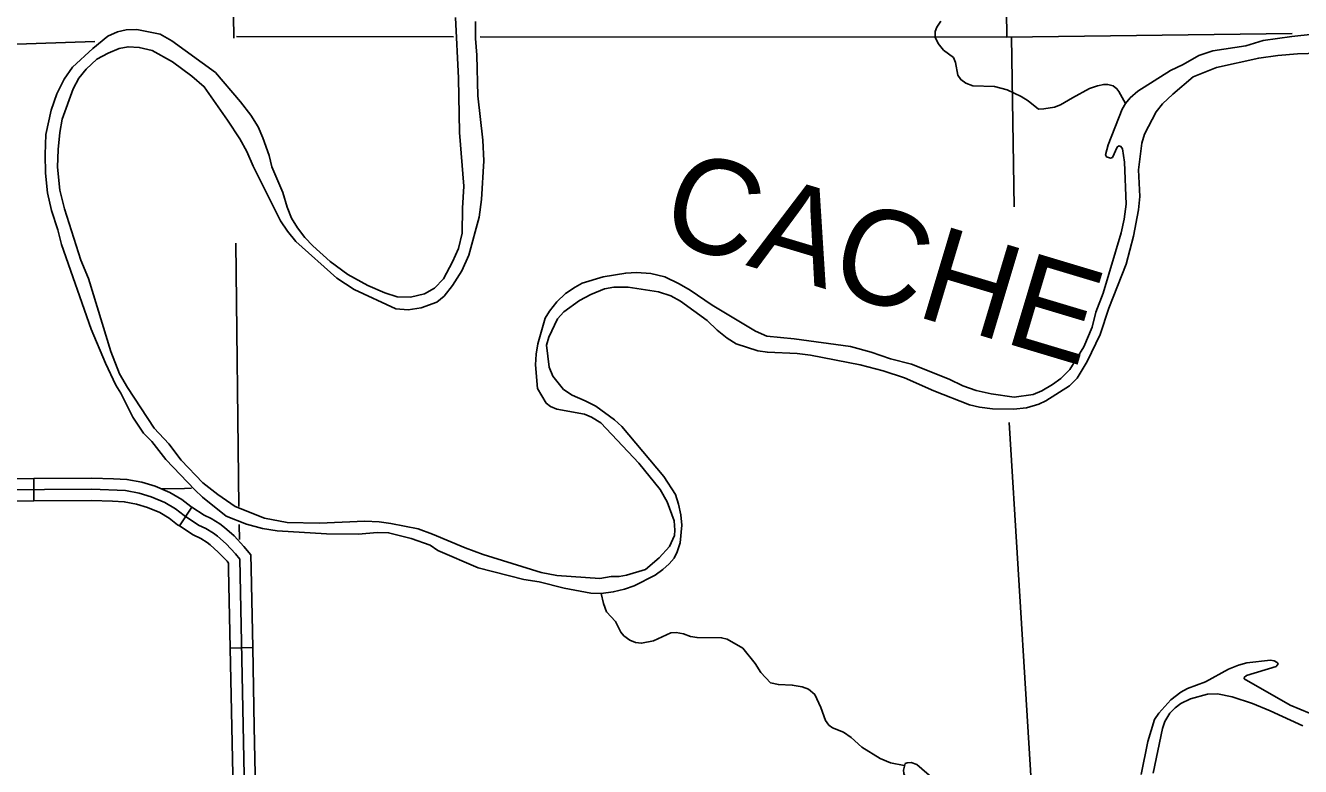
# Model space of a CAD drawing. Extents: x 1084508 to 1142749, y 1057638 to 1093403.
# Drawn here: x 1087461 to 1090132, y 1065503 to 1067055 of the extents above; entities that cross this region are included whole.
import ezdxf

# ---------------------------------------------------------------- set-up
doc = ezdxf.new("R2010")
doc.units = 0
for name, color, linetype in [('Level 35', 7, 'Continuous'), ('Level 4', 7, 'Continuous'), ('Level 45', 7, 'Continuous'), ('Level 5', 7, 'Continuous'), ('Level 7', 7, 'Continuous'), ('Level 9', 7, 'Continuous')]:
    doc.layers.add(name, color=color, linetype=linetype)

msp = doc.modelspace()

# ---------------------------------------------------------------- linework, layer by layer
at = {"layer": 'Level 35'}
for points in [[(1089765.6, 1066892), (1089751.9, 1066917.3), (1089747.7, 1066922.9), (1089739.7, 1066928.9), (1089728.6, 1066932), (1089720.1, 1066932), (1089706.7, 1066929.1), (1089690.3, 1066923.2), (1089654.6, 1066904.1), (1089629.7, 1066889.1), (1089616.7, 1066884), (1089594.2, 1066880.7), (1089583.6, 1066880.4), (1089561.7, 1066897.6), (1089547.3, 1066906.9), (1089517.4, 1066920.3), (1089491.5, 1066927.4), (1089446, 1066929.3), (1089431.4, 1066934.8), (1089420.8, 1066942), (1089414.6, 1066951.6), (1089409.7, 1066978.1), (1089404.9, 1066988.3), (1089384.4, 1067003.4), (1089373, 1067017.5), (1089366.6, 1067030.8), (1089366.5, 1067042.7), (1089370.3, 1067052), (1089378.4, 1067064.2)], [(1089302.2, 1065504.4), (1089273.1, 1065510.6), (1089251.9, 1065519.1), (1089213.5, 1065543.3), (1089190.9, 1065563.6), (1089174.9, 1065574.4), (1089151.4, 1065584), (1089144.3, 1065589.4), (1089136.8, 1065599.2), (1089127.2, 1065626), (1089114.4, 1065653.5), (1089101.5, 1065664.4), (1089087.8, 1065669.9), (1089067.4, 1065673.4), (1089038.5, 1065674.3), (1089022.1, 1065678.2), (1089001.3, 1065699.5), (1088989.5, 1065718.3), (1088963.7, 1065750.5), (1088930.8, 1065769.5), (1088919.4, 1065772.3), (1088868, 1065772.8), (1088854.4, 1065775.2), (1088839.6, 1065780.4), (1088823.8, 1065783.3), (1088813.1, 1065782.9), (1088776.7, 1065766), (1088751.5, 1065760.8), (1088738.9, 1065762.3), (1088726.8, 1065767.5), (1088714.7, 1065776.3), (1088708.1, 1065783.9), (1088696.7, 1065806.8), (1088678.2, 1065826.9), (1088671.7, 1065844.3), (1088667, 1065865.3)], [(1089387.7, 1065303.6), (1089397.6, 1065362.5), (1089395.9, 1065395.5), (1089387.1, 1065437), (1089378.3, 1065455.9), (1089364.5, 1065475.3), (1089328.7, 1065507.1), (1089316.7, 1065511.1), (1089308.2, 1065510.5), (1089304.2, 1065508.8), (1089300.3, 1065495.2), (1089301.5, 1065488), (1089324.3, 1065439.7), (1089336.5, 1065421.8), (1089342.3, 1065405), (1089344.2, 1065375.2), (1089339.6, 1065344.3), (1089334.2, 1065325.5), (1089326.4, 1065281.4)]]:
    msp.add_lwpolyline(points, dxfattribs=at)
at = {"layer": 'Level 4'}
for points in [[(1088357.4, 1067031.7), (1087903, 1067032)], [(1090114.7, 1067038.8), (1089516.4, 1067031), (1088413.2, 1067031.7)], [(1087606.3, 1067022), (1086867.5, 1066996.4)]]:
    msp.add_lwpolyline(points, dxfattribs=at)
at = {"layer": 'Level 45'}
for p, q in [((1087478.1, 1066106.3), (1087478.4, 1066059.2)), ((1087809.5, 1066045.9), (1087783.4, 1066006.7)), ((1087936.8, 1065751.7), (1087889.7, 1065750.7))]:
    msp.add_line(p, q, dxfattribs=at)
for points in [[(1087478.1, 1066106.3), (1087312.4, 1066105.2)], [(1087644.9, 1066105.4), (1087600, 1066107.1), (1087478.1, 1066106.3)], [(1087809.5, 1066045.9), (1087807.1, 1066047.5), (1087788.5, 1066061.9), (1087763.3, 1066077), (1087732.1, 1066090.2), (1087704.3, 1066098.4), (1087673.1, 1066104.3), (1087644.9, 1066105.4)], [(1087670.4, 1066080.8), (1087599.6, 1066083.6), (1087104.7, 1066080.2), (1086147.2, 1066060.1)], [(1087909.5, 1065937.3), (1087900.7, 1065948.2), (1087881.2, 1065968.9), (1087863, 1065985.2), (1087854.5, 1065991.7), (1087838.9, 1066001.2), (1087823.2, 1066008.5), (1087793.3, 1066028.4), (1087775.2, 1066042.4), (1087752.6, 1066056), (1087724.2, 1066068), (1087698.7, 1066075.4), (1087670.4, 1066080.8)], [(1087478.4, 1066059.2), (1087312.7, 1066058.1)], [(1087643, 1066058.3), (1087599.2, 1066060), (1087478.4, 1066059.2)], [(1087783.4, 1066006.7), (1087779.5, 1066009.3), (1087761.9, 1066023), (1087742, 1066034.9), (1087716.3, 1066045.7), (1087693.2, 1066052.5), (1087667.8, 1066057.4), (1087643, 1066058.3)], [(1087933.5, 1065917.3), (1087932.9, 1065945.9), (1087918.4, 1065963.7), (1087897.6, 1065985.8), (1087878, 1066003.4), (1087867.8, 1066011.2), (1087850, 1066022), (1087834.8, 1066029.1), (1087809.5, 1066045.9)], [(1087886.4, 1065916.4), (1087886.1, 1065928.7), (1087883, 1065932.7), (1087864.7, 1065952.1), (1087848, 1065967), (1087841.1, 1065972.3), (1087827.8, 1065980.4), (1087811.7, 1065987.9), (1087783.4, 1066006.7)], [(1087923.6, 1065240.9), (1087909.5, 1065937.3)], [(1087889.7, 1065750.7), (1087886.4, 1065916.4)], [(1087936.8, 1065751.7), (1087933.5, 1065917.3)], [(1087893.1, 1065585), (1087889.7, 1065750.7)], [(1087940.2, 1065586), (1087936.8, 1065751.7)], [(1087896.5, 1065419.3), (1087893.1, 1065585)], [(1087943.5, 1065420.3), (1087940.2, 1065586)]]:
    msp.add_lwpolyline(points, dxfattribs=at)
at = {"layer": 'Level 5'}
for points in [[(1089501.6, 1068232), (1089517.2, 1067031)], [(1087897.2, 1067029), (1087897.2, 1067032), (1087890.2, 1067442.6)], [(1089526.8, 1067031.1), (1089532.2, 1066675.2)], [(1087901.4, 1066599.2), (1087908, 1066047.2)], [(1089521.6, 1066223.4), (1089578.2, 1065301.8)], [(1087908.5, 1066009.8), (1087908.9, 1065978)]]:
    msp.add_lwpolyline(points, dxfattribs=at)
at = {"layer": 'Level 7'}
msp.add_lwpolyline([(1087808.6, 1066086), (1087793.6, 1066085.1), (1087747.3, 1066084.5)], dxfattribs=at)
at = {"layer": 'Level 9'}
for points in [[(1087994.8, 1066646.3), (1088009.6, 1066624.7), (1088027.5, 1066602.7), (1088113, 1066525.6), (1088149.2, 1066502.3), (1088237, 1066461.5), (1088262.5, 1066459.5), (1088289.9, 1066463.8), (1088322.4, 1066475.6), (1088337.7, 1066488.3), (1088355.5, 1066510.6), (1088374.8, 1066541.4), (1088389.4, 1066574.3), (1088411.3, 1066653.9), (1088416.4, 1066690.6), (1088421, 1066771.9), (1088419.3, 1066814.9), (1088408.5, 1066907.9), (1088406.7, 1066993.1), (1088403.4, 1067027.9), (1088403.8, 1067063.7)], [(1088030.4, 1066631.7), (1088046.1, 1066611.2), (1088062.6, 1066593.5), (1088099.4, 1066561), (1088136, 1066533.3), (1088177.8, 1066510.5), (1088213.4, 1066495.3), (1088239.6, 1066487), (1088267.5, 1066486.4), (1088296.8, 1066493), (1088317.7, 1066504.7), (1088336.5, 1066524.5), (1088355.7, 1066560.3), (1088368.3, 1066588.1), (1088375.7, 1066620.4), (1088376.6, 1066672.6), (1088379.5, 1066718.6), (1088370.2, 1066831.2), (1088367.8, 1066945.2), (1088361.9, 1067072.4)], [(1088823, 1066072.5), (1088829.2, 1066052.6), (1088833.7, 1066029.8), (1088835.7, 1066008.2), (1088832.2, 1065971.3), (1088826.5, 1065952.2), (1088819.7, 1065939.1), (1088809.5, 1065927.1), (1088796.4, 1065915.1), (1088780.1, 1065903.5), (1088736, 1065881), (1088715.6, 1065874.1), (1088692.3, 1065868.6), (1088667, 1065865.3), (1088645.4, 1065865.5), (1088589.5, 1065876.2), (1088537.1, 1065889.3), (1088504.7, 1065894.5), (1088409.5, 1065919.1), (1088324.4, 1065955), (1088308.4, 1065966.4), (1088268.8, 1065980.2), (1088221.4, 1065992.5), (1088198.5, 1065993), (1088158.1, 1065989.8), (1088091.1, 1065990.4), (1087988.1, 1065996.5), (1087957.2, 1066001.4), (1087923.7, 1066010.4), (1087881.2, 1066027.2), (1087831.6, 1066067.1), (1087815.2, 1066082.3), (1087754.8, 1066145.7), (1087725.1, 1066183.7), (1087707.9, 1066201.1), (1087685.9, 1066234.6), (1087660.8, 1066284.7), (1087650.2, 1066302), (1087628.3, 1066347.5), (1087598.5, 1066418.9), (1087536, 1066596.7), (1087528.8, 1066626.9), (1087515.3, 1066668), (1087506.9, 1066704.5), (1087502.7, 1066746.2), (1087502.1, 1066784.8), (1087503.6, 1066826.7), (1087514.5, 1066878), (1087526.5, 1066912.3), (1087541.9, 1066942.7), (1087559.5, 1066967.8), (1087601.5, 1067006.9), (1087633.3, 1067033.1), (1087653.4, 1067042.3), (1087671.7, 1067046.6), (1087693.9, 1067047.1), (1087742.8, 1067037.3), (1087767.1, 1067023.4), (1087858.5, 1066956.9), (1087911, 1066895.4), (1087933.2, 1066867.2), (1087948.4, 1066842.8), (1087958.2, 1066820.2), (1087971.3, 1066783.2), (1087977.1, 1066759.2), (1087999.8, 1066705.5), (1088009.2, 1066674.7), (1088018.4, 1066651.4), (1088030.4, 1066631.7)], [(1090197.1, 1067041.5), (1090114.2, 1067032.6), (1090054.1, 1067023.8), (1090017.7, 1067012.8), (1089948.8, 1067002.1), (1089919.4, 1066992.6), (1089886.7, 1066973.9), (1089860.2, 1066961.1), (1089791.7, 1066918), (1089775.6, 1066903.6), (1089765.6, 1066892), (1089758.5, 1066879.8), (1089729.2, 1066805), (1089723.9, 1066784.4), (1089725.6, 1066780), (1089734.5, 1066777.5), (1089738.2, 1066778.5), (1089747.9, 1066800.5), (1089751.5, 1066802.9), (1089755.9, 1066802.1), (1089759.2, 1066797.1), (1089763.9, 1066768.7), (1089767.1, 1066680.8), (1089763, 1066649.8), (1089756.7, 1066621), (1089719.1, 1066494.3), (1089703.8, 1066454.5), (1089695.7, 1066423.1), (1089678.6, 1066381.7), (1089648.8, 1066334.2), (1089629.9, 1066315.9), (1089612.5, 1066302.8), (1089590.3, 1066289.8), (1089572.4, 1066282), (1089532.1, 1066276.9), (1089484.3, 1066283.8), (1089452.7, 1066290.3), (1089424.8, 1066300.4), (1089396.5, 1066314.3), (1089317.2, 1066345.6), (1089273.2, 1066357.1), (1089232.7, 1066370.8), (1089189.4, 1066382.9), (1089071.3, 1066398.9), (1089013.8, 1066404.5), (1088990.3, 1066414.8), (1088899.5, 1066469.3), (1088853.7, 1066500.8), (1088830.7, 1066513.9), (1088800.2, 1066528.7), (1088770.8, 1066535.6), (1088741, 1066537.7), (1088718.4, 1066536.7), (1088671.4, 1066528.5), (1088627, 1066515.1), (1088612.2, 1066507.4), (1088592, 1066493.8), (1088574.3, 1066476.6), (1088559, 1066456.9), (1088549.4, 1066441.8), (1088534.6, 1066388.2)], [(1088534.6, 1066388.2), (1088530.8, 1066367), (1088529.4, 1066344.3), (1088533.5, 1066294.5), (1088552, 1066264), (1088560.7, 1066257), (1088574.4, 1066251.5), (1088632, 1066241.1), (1088647, 1066234.7), (1088666.2, 1066222.7), (1088746, 1066138.2), (1088790.7, 1066083.1), (1088805.6, 1066057.5), (1088820, 1066017.1), (1088821.3, 1065997.7), (1088820.4, 1065986.9), (1088809.9, 1065963.3), (1088788.7, 1065940), (1088759.7, 1065915.1), (1088719.7, 1065903.5), (1088704.7, 1065901.1), (1088687.8, 1065900.5), (1088664.4, 1065896.9), (1088573.9, 1065903.1), (1088541.5, 1065908.9), (1088419.9, 1065947.1), (1088381.9, 1065960.6), (1088313.3, 1065989.8), (1088283.5, 1066000.8), (1088226.1, 1066012.1), (1088201.8, 1066015.4), (1088171.7, 1066016.9), (1088076.9, 1066012.6), (1088008.8, 1066014.1), (1087961.5, 1066023.2), (1087900, 1066047.3), (1087864, 1066072.6), (1087832.5, 1066097.3), (1087787.2, 1066144.6), (1087761.3, 1066178.9), (1087730.2, 1066211.6), (1087674.5, 1066296.5), (1087657.6, 1066325.2), (1087639.8, 1066372.4), (1087592.6, 1066524.9), (1087576.9, 1066563.7), (1087542.7, 1066671.4), (1087532.7, 1066710.4), (1087528, 1066758.6), (1087529.4, 1066795.2), (1087532.9, 1066831.1), (1087537.6, 1066858.9), (1087560.4, 1066922.9), (1087572.2, 1066944.7), (1087587.9, 1066964), (1087610.1, 1066984.6), (1087634.1, 1066997.3), (1087657.3, 1067006.9), (1087675.7, 1067010.9), (1087699.2, 1067009.5), (1087725.8, 1067002.8), (1087768.8, 1066979.4), (1087809.3, 1066949.3), (1087835.4, 1066927.2), (1087884.3, 1066856.8), (1087909.7, 1066817.7), (1087924.6, 1066791.4), (1087937.5, 1066760.4), (1087994.8, 1066646.3)], [(1090171, 1066997.4), (1090126.4, 1066995.7), (1090085.1, 1066992.4), (1090044.9, 1066987), (1089956.2, 1066967.7), (1089907.3, 1066947.6), (1089864.6, 1066911.3), (1089843.3, 1066891.4), (1089829.8, 1066874.6), (1089805.6, 1066827.6), (1089800.2, 1066808.9), (1089792.6, 1066752.7), (1089795.4, 1066697.1), (1089793.1, 1066669), (1089782.4, 1066614), (1089767, 1066555), (1089730.8, 1066462.9), (1089712.5, 1066407.9), (1089685.5, 1066351.4), (1089664.4, 1066316.7), (1089648.6, 1066300.5), (1089598.8, 1066269), (1089584, 1066261.6), (1089557.9, 1066254.1), (1089531.1, 1066251.1), (1089486.9, 1066252.1), (1089459.5, 1066255.9), (1089438.7, 1066260.6), (1089363.8, 1066289.9), (1089302.7, 1066316.8), (1089257.8, 1066331.4), (1089209.7, 1066344.3), (1089105.3, 1066364.8), (1089077.7, 1066368), (1089015.2, 1066370.6), (1088995, 1066374), (1088950.1, 1066388), (1088930.9, 1066400.2), (1088910.3, 1066416.9), (1088889, 1066437.5), (1088833.1, 1066477.9), (1088812.7, 1066489.1), (1088786.8, 1066497.4), (1088723.8, 1066507), (1088693.7, 1066507.2), (1088673.7, 1066503.8), (1088645.3, 1066491.8), (1088621.3, 1066479.4), (1088588.8, 1066455.4), (1088575.2, 1066440.5), (1088557.6, 1066402.5), (1088552.2, 1066385.6), (1088557.7, 1066339.3), (1088565.9, 1066320.4), (1088588.1, 1066292.8), (1088606, 1066280.8), (1088633.6, 1066269.1), (1088655.6, 1066257.6), (1088695.1, 1066229.3), (1088710.6, 1066215.1), (1088798.3, 1066110.1), (1088823, 1066072.5)], [(1089798.2, 1065486), (1089812.6, 1065554.7), (1089826.2, 1065600.8), (1089835.8, 1065614.3), (1089860.6, 1065642.1), (1089881.4, 1065658.5), (1089895.8, 1065666.2), (1089933, 1065680.3), (1089981.7, 1065706.5), (1090002.1, 1065715), (1090019.8, 1065719.7), (1090069.4, 1065725.4), (1090077, 1065724), (1090083.4, 1065720.5), (1090085.3, 1065717.7), (1090081.1, 1065712.2), (1090019.1, 1065693.2), (1090014.5, 1065689), (1090014.6, 1065686.5), (1090111, 1065631.5), (1090151.3, 1065614.2)], [(1089823.8, 1065488.4), (1089843.4, 1065582.1), (1089848.2, 1065596.8), (1089858.6, 1065614.4), (1089869.6, 1065625.4), (1089881.5, 1065634.6), (1089901.8, 1065644.7), (1089937.6, 1065654.4), (1089958.6, 1065654.8), (1089989.5, 1065648.5), (1090031.6, 1065634.8), (1090069.1, 1065619.4), (1090137.5, 1065587.7)]]:
    msp.add_lwpolyline(points, dxfattribs=at)

# ---------------------------------------------------------------- texts
msp.add_text('CACHE', height=198.88, rotation=343.3194, dxfattribs=at).set_placement((1088784.5, 1066608.6))

doc.saveas('drawing.dxf')
